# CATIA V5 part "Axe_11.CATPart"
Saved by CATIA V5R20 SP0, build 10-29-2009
Part number: Axe_11
Publications: "Plan zx"
Bounding box of the stored display mesh (mm): x -29.999 to 29.999, y 0 to 550, z -29.984 to 29.984
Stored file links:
  C:\Users\Thinkmotion2\Desktop\Pack 2\CFAO_2010\abaussand\CFAO_abaussand_Catia_V5R20\Axe_11.CATPart
  C:\Users\Thinkmotion2\Desktop\Pack 2\CFAO_2010\abaussand\CFAO_abaussand_Catia_V5R20\abaussand_2.CATProduct
  C:\Users\Thinkmotion2\Desktop\Pack 2\CFAO_2010\abaussand\CFAO_abaussand_Catia_V5R20\support_17.CATPart
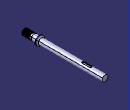
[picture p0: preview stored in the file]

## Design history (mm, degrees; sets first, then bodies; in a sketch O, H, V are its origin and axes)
External parameters (linked from other documents)
  `External.Diamètre_axe_41` = 40 mm
Body1 (main body)
  Sketch1 on xy-plane, origin (0, 0, 0), H (1, 0, 0), V (0, 1, 0)
    line L1 (0, 0) -> (20, 0)
    line L2 (20, 550) -> (0, 550)
    line L3 (0, 550) -> (0, 0)
    point P1 (20, 0)
    line L4 (20, 0) -> (20, 50)
    point P4 (20, 100)
    line L5 (30, 105) -> (20, 113.5)
    point P6 (20, 113.5)
    line L6 (20, 113.5) -> (20, 550)
    line L7 (30, 105) -> (30, 100)
    line L8 (30, 100) -> (20, 100)
    line L9 (20, 50) -> (15, 50)
    line L10 (15, 50) -> (15, 65)
    line L11 (15, 65) -> (20, 65)
    point P11 (20, 65)
    line L12 (20, 65) -> (20, 100)
    length L2 = 20 {= `External.Diamètre_axe_41` /2}
    length L3 = 550
    length L8 = 10
    length L7 = 5
    distance P1 P4 = 100
    length L4 = 50
    length L10 = 15
    distance L10 L3 = 15
    distance P6 P4 = 13.5
    horizontal: L1 H, L2 H, L8 H, L9 H, L11 H
    vertical: L3 V, L4 V, L6 V, L7 V, L10 V, L12 V
    coincidence: P6 L4, P11 L4, L4 L12
  Shaft1: profile Sketch1, axis Sketch1.L3, angle 360
  Sketch2 on zx-plane, origin (0, 0, 0), H (-1, 0, 0), V (0, 0, 1)
    line L1 (-1, 21) -> (1, 21)
    line L2 (1, 21) -> (1, 0)
    line L3 (1, 0) -> (-1, 0)
    line L4 (-1, 0) -> (-1, 21)
    length L1 = 2
    distance L2 V = 1
    distance L1 H = 21
    horizontal: L1 H, L3 H
    vertical: L2 V, L4 V
    coincidence: L3 H
  Pad1: profile Sketch2, direction (0, 1, 0), length 50
  CircPattern1: of Pad1, instances 30, angular step 12, axis from face of Shaft1 from Sketch1.L4
  Point1: (0, 170, 0)
  Line1: type Normal, RefPoint Point1, RefSkin yz-plane, Start -20, End 20
  Sketch3 on xy-plane, origin (0, 0, 0), H (1, 0, 0), V (0, 1, 0)
    line L1 (-7.5, 450) -> (-7.5, 400)
    arc A1 centre (0, 400) radius 7.5 from (-7.5, 400) to (7.5, 400) ccw
    point P3 (0, 400)
    line L2 (7.5, 400) -> (7.5, 450)
    arc A2 centre (0, 450) radius 7.5 from (7.5, 450) to (-7.5, 450) ccw
    length L2 = 50
    distance L2 L1 = 15
    distance P3 H = 400
    vertical: L1 V
    tangency: A1 L1, L2 A1, A2 L1, A2 L2
    coincidence: P3 V
  Pocket1: profile Sketch3, direction (0, 0, -1), length -13, opposite side through (limit type 3)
